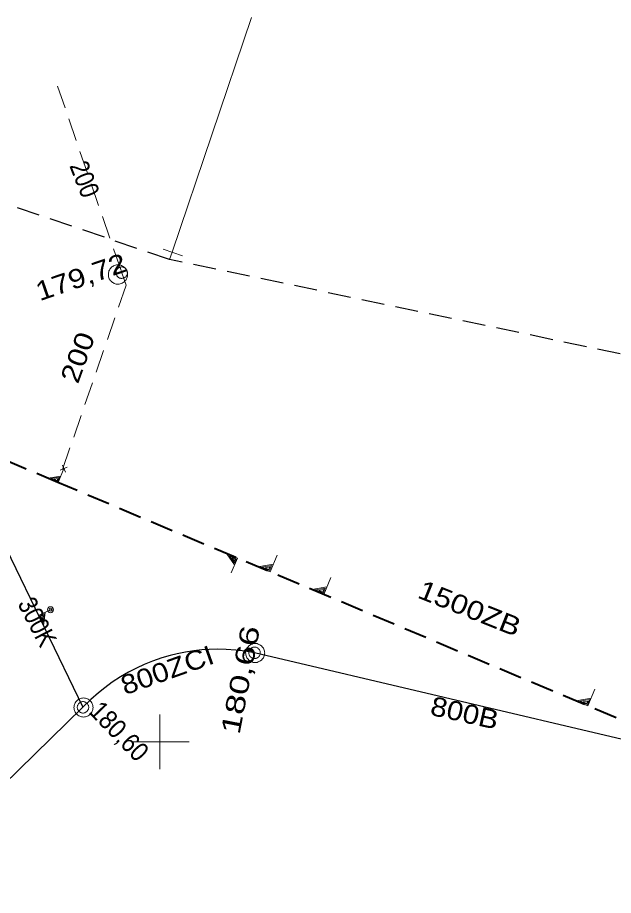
# Model space of a CAD drawing. Extents: x -740851 to -738888, y -1041382 to -1040235.
# Drawn here: x -740357.45 to -740326.27, y -1040408.04 to -1040362.13 of the extents above; entities that cross this region are included whole.
import ezdxf

# ---------------------------------------------------------------- set-up
doc = ezdxf.new("R2010")
doc.units = 0
doc.header["$LTSCALE"] = 0.4
doc.linetypes.add('MEDIUM_DASHED', pattern=[4.5, 3, -1.5])
for name, color, linetype, lineweight in [('1', 7, 'Continuous', 13), ('18', 7, 'Continuous', 13), ('38', 7, 'Continuous', 13), ('48', 7, 'MEDIUM_DASHED', 13), ('8', 7, 'Continuous', 13)]:
    doc.layers.add(name, color=color, linetype=linetype, lineweight=lineweight)

msp = doc.modelspace()

# ---------------------------------------------------------------- linework, layer by layer
at = {"layer": '1'}
for p, q in [((-740350, -1040398.571), (-740350, -1040401.429)), ((-740351.48, -1040400), (-740348.48, -1040400))]:
    msp.add_line(p, q, dxfattribs=at)
at = {"layer": '18'}
for p, q in [((-740355.216, -1040385.791), (-740354.854, -1040385.643)), ((-740355.099, -1040385.533), (-740354.95, -1040385.899))]:
    msp.add_line(p, q, dxfattribs=at)
at = {"layer": '18', "lineweight": 25}
msp.add_line((-740321.54, -1040400.88), (-740345.05, -1040395.35), dxfattribs=at)
at = {"layer": '18'}
for points in [[(-740352.39, -1040376.036), (-740352.339, -1040376.045), (-740352.292, -1040376.064), (-740352.237, -1040376.064), (-740352.182, -1040376.064), (-740352.128, -1040376.065), (-740352.079, -1040376.051), (-740352.029, -1040376.038), (-740351.977, -1040376.016), (-740351.933, -1040375.989), (-740351.89, -1040375.963), (-740351.852, -1040375.923), (-740351.814, -1040375.884), (-740351.777, -1040375.844), (-740351.758, -1040375.797), (-740351.729, -1040375.754), (-740351.72, -1040375.703), (-740351.701, -1040375.655), (-740351.701, -1040375.601), (-740351.701, -1040375.546), (-740351.701, -1040375.491), (-740351.714, -1040375.442), (-740351.727, -1040375.393), (-740351.75, -1040375.34), (-740351.776, -1040375.297), (-740351.802, -1040375.254), (-740351.842, -1040375.216), (-740351.882, -1040375.178), (-740351.921, -1040375.14), (-740351.968, -1040375.121), (-740352.012, -1040375.093), (-740352.063, -1040375.084), (-740352.11, -1040375.065), (-740352.165, -1040375.065), (-740352.219, -1040375.065), (-740352.274, -1040375.065), (-740352.323, -1040375.078), (-740352.372, -1040375.091), (-740352.425, -1040375.113), (-740352.468, -1040375.14), (-740352.512, -1040375.166), (-740352.55, -1040375.206), (-740352.587, -1040375.245), (-740352.625, -1040375.285), (-740352.644, -1040375.332), (-740352.672, -1040375.375), (-740352.682, -1040375.426), (-740352.701, -1040375.474), (-740352.701, -1040375.528), (-740352.701, -1040375.583), (-740352.701, -1040375.638), (-740352.688, -1040375.687), (-740352.674, -1040375.736), (-740352.652, -1040375.789), (-740352.625, -1040375.832), (-740352.599, -1040375.875), (-740352.559, -1040375.913), (-740352.52, -1040375.951), (-740352.48, -1040375.989), (-740352.433, -1040376.008)], [(-740352.111, -1040375.748), (-740352.084, -1040375.759), (-740352.054, -1040375.764), (-740352.024, -1040375.77), (-740351.991, -1040375.77), (-740351.957, -1040375.764), (-740351.928, -1040375.757), (-740351.899, -1040375.749), (-740351.868, -1040375.736), (-740351.842, -1040375.72), (-740351.817, -1040375.705), (-740351.789, -1040375.683), (-740351.767, -1040375.66), (-740351.75, -1040375.635), (-740351.733, -1040375.609), (-740351.722, -1040375.581), (-740351.711, -1040375.554), (-740351.706, -1040375.524), (-740351.7, -1040375.494), (-740351.7, -1040375.461), (-740351.706, -1040375.427), (-740351.713, -1040375.398), (-740351.721, -1040375.369), (-740351.734, -1040375.338), (-740351.75, -1040375.312), (-740351.765, -1040375.287), (-740351.787, -1040375.259), (-740351.81, -1040375.237), (-740351.835, -1040375.22), (-740351.861, -1040375.203), (-740351.889, -1040375.192), (-740351.916, -1040375.181), (-740351.946, -1040375.176), (-740351.976, -1040375.17), (-740352.009, -1040375.17), (-740352.043, -1040375.176), (-740352.072, -1040375.183), (-740352.101, -1040375.191), (-740352.132, -1040375.204), (-740352.158, -1040375.22), (-740352.183, -1040375.235), (-740352.211, -1040375.257), (-740352.233, -1040375.28), (-740352.25, -1040375.305), (-740352.267, -1040375.331), (-740352.278, -1040375.359), (-740352.289, -1040375.386), (-740352.294, -1040375.416), (-740352.3, -1040375.446), (-740352.3, -1040375.479), (-740352.294, -1040375.513), (-740352.287, -1040375.542), (-740352.279, -1040375.571), (-740352.266, -1040375.602), (-740352.25, -1040375.628), (-740352.235, -1040375.653), (-740352.213, -1040375.681), (-740352.19, -1040375.703), (-740352.165, -1040375.72), (-740352.139, -1040375.737)], [(-740344.52, -1040395.36), (-740344.53, -1040395.31), (-740344.53, -1040395.26), (-740344.55, -1040395.21), (-740344.57, -1040395.16), (-740344.59, -1040395.11), (-740344.62, -1040395.07), (-740344.65, -1040395.03), (-740344.69, -1040394.99), (-740344.73, -1040394.96), (-740344.77, -1040394.93), (-740344.82, -1040394.91), (-740344.87, -1040394.89), (-740344.92, -1040394.87), (-740344.97, -1040394.87), (-740345.02, -1040394.86), (-740345.07, -1040394.87), (-740345.12, -1040394.87), (-740345.17, -1040394.89), (-740345.22, -1040394.91), (-740345.27, -1040394.93), (-740345.31, -1040394.96), (-740345.35, -1040394.99), (-740345.39, -1040395.03), (-740345.42, -1040395.07), (-740345.45, -1040395.11), (-740345.47, -1040395.16), (-740345.49, -1040395.21), (-740345.51, -1040395.26), (-740345.51, -1040395.31), (-740345.52, -1040395.36), (-740345.51, -1040395.41), (-740345.51, -1040395.46), (-740345.49, -1040395.51), (-740345.47, -1040395.56), (-740345.45, -1040395.61), (-740345.42, -1040395.65), (-740345.39, -1040395.69), (-740345.35, -1040395.73), (-740345.31, -1040395.76), (-740345.27, -1040395.79), (-740345.22, -1040395.81), (-740345.17, -1040395.83), (-740345.12, -1040395.85), (-740345.07, -1040395.85), (-740345.02, -1040395.86), (-740344.97, -1040395.85), (-740344.92, -1040395.85), (-740344.87, -1040395.83), (-740344.82, -1040395.81), (-740344.77, -1040395.79), (-740344.73, -1040395.76), (-740344.69, -1040395.73), (-740344.65, -1040395.69), (-740344.62, -1040395.65), (-740344.59, -1040395.61), (-740344.57, -1040395.56), (-740344.55, -1040395.51), (-740344.53, -1040395.46), (-740344.53, -1040395.41)], [(-740344.75, -1040395.35), (-740344.75, -1040395.32), (-740344.756, -1040395.29), (-740344.762, -1040395.26), (-740344.774, -1040395.23), (-740344.792, -1040395.2), (-740344.81, -1040395.176), (-740344.828, -1040395.152), (-740344.852, -1040395.128), (-740344.876, -1040395.11), (-740344.9, -1040395.092), (-740344.93, -1040395.074), (-740344.96, -1040395.062), (-740344.99, -1040395.056), (-740345.02, -1040395.05), (-740345.05, -1040395.05), (-740345.08, -1040395.05), (-740345.11, -1040395.056), (-740345.14, -1040395.062), (-740345.17, -1040395.074), (-740345.2, -1040395.092), (-740345.224, -1040395.11), (-740345.248, -1040395.128), (-740345.272, -1040395.152), (-740345.29, -1040395.176), (-740345.308, -1040395.2), (-740345.326, -1040395.23), (-740345.338, -1040395.26), (-740345.344, -1040395.29), (-740345.35, -1040395.32), (-740345.35, -1040395.35), (-740345.35, -1040395.38), (-740345.344, -1040395.41), (-740345.338, -1040395.44), (-740345.326, -1040395.47), (-740345.308, -1040395.5), (-740345.29, -1040395.524), (-740345.272, -1040395.548), (-740345.248, -1040395.572), (-740345.224, -1040395.59), (-740345.2, -1040395.608), (-740345.17, -1040395.626), (-740345.14, -1040395.638), (-740345.11, -1040395.644), (-740345.08, -1040395.65), (-740345.05, -1040395.65), (-740345.02, -1040395.65), (-740344.99, -1040395.644), (-740344.96, -1040395.638), (-740344.93, -1040395.626), (-740344.9, -1040395.608), (-740344.876, -1040395.59), (-740344.852, -1040395.572), (-740344.828, -1040395.548), (-740344.81, -1040395.524), (-740344.792, -1040395.5), (-740344.774, -1040395.47), (-740344.762, -1040395.44), (-740344.756, -1040395.41), (-740344.75, -1040395.38)], [(-740353.5, -1040398.21), (-740353.51, -1040398.16), (-740353.51, -1040398.11), (-740353.53, -1040398.06), (-740353.55, -1040398.01), (-740353.57, -1040397.96), (-740353.6, -1040397.92), (-740353.63, -1040397.88), (-740353.67, -1040397.84), (-740353.71, -1040397.81), (-740353.75, -1040397.78), (-740353.8, -1040397.76), (-740353.85, -1040397.74), (-740353.9, -1040397.72), (-740353.95, -1040397.72), (-740354, -1040397.71), (-740354.05, -1040397.72), (-740354.1, -1040397.72), (-740354.15, -1040397.74), (-740354.2, -1040397.76), (-740354.25, -1040397.78), (-740354.29, -1040397.81), (-740354.33, -1040397.84), (-740354.37, -1040397.88), (-740354.4, -1040397.92), (-740354.43, -1040397.96), (-740354.45, -1040398.01), (-740354.47, -1040398.06), (-740354.49, -1040398.11), (-740354.49, -1040398.16), (-740354.5, -1040398.21), (-740354.49, -1040398.26), (-740354.49, -1040398.31), (-740354.47, -1040398.36), (-740354.45, -1040398.41), (-740354.43, -1040398.46), (-740354.4, -1040398.5), (-740354.37, -1040398.54), (-740354.33, -1040398.58), (-740354.29, -1040398.61), (-740354.25, -1040398.64), (-740354.2, -1040398.66), (-740354.15, -1040398.68), (-740354.1, -1040398.7), (-740354.05, -1040398.7), (-740354, -1040398.71), (-740353.95, -1040398.7), (-740353.9, -1040398.7), (-740353.85, -1040398.68), (-740353.8, -1040398.66), (-740353.75, -1040398.64), (-740353.71, -1040398.61), (-740353.67, -1040398.58), (-740353.63, -1040398.54), (-740353.6, -1040398.5), (-740353.57, -1040398.46), (-740353.55, -1040398.41), (-740353.53, -1040398.36), (-740353.51, -1040398.31), (-740353.51, -1040398.26)], [(-740353.73, -1040398.2), (-740353.73, -1040398.17), (-740353.736, -1040398.14), (-740353.742, -1040398.11), (-740353.754, -1040398.08), (-740353.772, -1040398.05), (-740353.79, -1040398.026), (-740353.808, -1040398.002), (-740353.832, -1040397.978), (-740353.856, -1040397.96), (-740353.88, -1040397.942), (-740353.91, -1040397.924), (-740353.94, -1040397.912), (-740353.97, -1040397.906), (-740354, -1040397.9), (-740354.03, -1040397.9), (-740354.06, -1040397.9), (-740354.09, -1040397.906), (-740354.12, -1040397.912), (-740354.15, -1040397.924), (-740354.18, -1040397.942), (-740354.204, -1040397.96), (-740354.228, -1040397.978), (-740354.252, -1040398.002), (-740354.27, -1040398.026), (-740354.288, -1040398.05), (-740354.306, -1040398.08), (-740354.318, -1040398.11), (-740354.324, -1040398.14), (-740354.33, -1040398.17), (-740354.33, -1040398.2), (-740354.33, -1040398.23), (-740354.324, -1040398.26), (-740354.318, -1040398.29), (-740354.306, -1040398.32), (-740354.288, -1040398.35), (-740354.27, -1040398.374), (-740354.252, -1040398.398), (-740354.228, -1040398.422), (-740354.204, -1040398.44), (-740354.18, -1040398.458), (-740354.15, -1040398.476), (-740354.12, -1040398.488), (-740354.09, -1040398.494), (-740354.06, -1040398.5), (-740354.03, -1040398.5), (-740354, -1040398.5), (-740353.97, -1040398.494), (-740353.94, -1040398.488), (-740353.91, -1040398.476), (-740353.88, -1040398.458), (-740353.856, -1040398.44), (-740353.832, -1040398.422), (-740353.808, -1040398.398), (-740353.79, -1040398.374), (-740353.772, -1040398.35), (-740353.754, -1040398.32), (-740353.742, -1040398.29), (-740353.736, -1040398.26), (-740353.73, -1040398.23)]]:
    msp.add_lwpolyline(points, close=True, dxfattribs=at)
at = {"layer": '18', "linetype": 'MEDIUM_DASHED', "lineweight": 40}
msp.add_lwpolyline([(-740306.23, -1040407.14), (-740355.337, -1040386.443), (-740362.58, -1040383.39)], dxfattribs=at)
at = {"layer": '18'}
for points in [[(-740355.027, -1040385.713), (-740355.335, -1040386.442), (-740355.854, -1040386.223), (-740355.196, -1040386.113)], [(-740355.265, -1040386.17), (-740355.354, -1040386.382), (-740355.687, -1040386.242), (-740355.262, -1040386.171)], [(-740355.336, -1040386.23), (-740355.38, -1040386.336), (-740355.551, -1040386.265), (-740355.332, -1040386.232)], [(-740346.271, -1040391.169), (-740345.947, -1040390.4), (-740346.495, -1040390.169), (-740346.093, -1040390.747)], [(-740346.101, -1040390.653), (-740346.006, -1040390.429), (-740346.357, -1040390.282), (-740346.097, -1040390.655)], [(-740346.107, -1040390.555), (-740346.06, -1040390.443), (-740346.24, -1040390.368), (-740346.104, -1040390.557)], [(-740343.872, -1040390.235), (-740344.243, -1040391.116), (-740344.872, -1040390.851), (-740344.076, -1040390.719)], [(-740344.159, -1040390.787), (-740344.267, -1040391.044), (-740344.669, -1040390.875), (-740344.155, -1040390.789)], [(-740344.244, -1040390.86), (-740344.299, -1040390.989), (-740344.505, -1040390.902), (-740344.24, -1040390.862)], [(-740341.061, -1040391.42), (-740341.433, -1040392.301), (-740342.061, -1040392.036), (-740341.265, -1040391.903)], [(-740341.349, -1040391.972), (-740341.457, -1040392.228), (-740341.858, -1040392.059), (-740341.344, -1040391.974)], [(-740341.434, -1040392.045), (-740341.488, -1040392.173), (-740341.694, -1040392.086), (-740341.43, -1040392.047)], [(-740355.59, -1040393.03), (-740356.35, -1040393.398), (-740356.088, -1040393.94), (-740356.007, -1040393.232)], [(-740356.064, -1040393.309), (-740356.286, -1040393.416), (-740356.118, -1040393.762), (-740356.066, -1040393.305)], [(-740356.125, -1040393.387), (-740356.235, -1040393.441), (-740356.149, -1040393.619), (-740356.126, -1040393.384)], [(-740327.239, -1040397.245), (-740327.61, -1040398.126), (-740328.239, -1040397.861), (-740327.443, -1040397.729)], [(-740327.526, -1040397.798), (-740327.634, -1040398.054), (-740328.036, -1040397.885), (-740327.522, -1040397.8)], [(-740327.611, -1040397.871), (-740327.665, -1040397.999), (-740327.871, -1040397.912), (-740327.607, -1040397.873)]]:
    msp.add_lwpolyline(points, dxfattribs=at)
at = {"layer": '18', "lineweight": 25}
for points in [[(-740358.04, -1040389.9), (-740354.03, -1040398.2), (-740364.11, -1040408.04)], [(-740345.05, -1040395.35), (-740345.542, -1040395.266), (-740346.028, -1040395.208), (-740346.536, -1040395.173), (-740346.991, -1040395.165), (-740347.419, -1040395.176), (-740347.803, -1040395.202), (-740348.223, -1040395.248), (-740348.659, -1040395.316), (-740349.097, -1040395.404), (-740349.466, -1040395.494), (-740349.899, -1040395.621), (-740350.387, -1040395.79), (-740350.822, -1040395.965), (-740351.227, -1040396.151), (-740351.648, -1040396.369), (-740352.061, -1040396.608), (-740352.496, -1040396.891), (-740352.887, -1040397.175), (-740353.215, -1040397.437), (-740353.614, -1040397.789), (-740354.03, -1040398.2)]]:
    msp.add_lwpolyline(points, dxfattribs=at)
at = {"layer": '18'}
for centre, radius in [((-740355.728, -1040393.097), 0.159), ((-740355.726, -1040393.097), 0.0786)]:
    msp.add_circle(centre, radius, dxfattribs=at)
at = {"layer": '38'}
for p, q in [((-740349.37, -1040374.4), (-740345.218, -1040362.126)), ((-740349.498, -1040374.778), (-740349.37, -1040374.4))]:
    msp.add_line(p, q, dxfattribs=at)
at = {"layer": '48'}
msp.add_line((-740355.36, -1040365.72), (-740352, -1040375.47), dxfattribs=at)
msp.add_lwpolyline([(-740352, -1040375.47), (-740351.77, -1040376.13), (-740355.337, -1040386.443)], dxfattribs=at)
at = {"layer": '8'}
msp.add_line((-740348.83, -1040374.583), (-740349.83, -1040374.244), dxfattribs=at)
at = {"layer": '8', "linetype": 'MEDIUM_DASHED', "lineweight": 25}
msp.add_lwpolyline([(-740297.337, -1040386.803), (-740297.74, -1040385.61), (-740349.498, -1040374.778), (-740359.17, -1040371.49)], dxfattribs=at)

# ---------------------------------------------------------------- texts
at = {"layer": '18'}
for s, rotation, width, p in [('200', 291.505, 0.85, (-740354.752, -1040369.876)), ('179,72', 19.016, 1.2, (-740356.293, -1040376.965)), ('200', 69.909, 1.2, (-740354.296, -1040381.329)), ('1500ZB', 338.306, 1.2, (-740336.589, -1040392.445)), ('300K', 297.421, 0.85, (-740357.473, -1040392.784)), ('180,66', 79.066, 1.4, (-740345.843, -1040399.669)), ('800ZCI', 19.617, 1.15, (-740351.828, -1040397.571)), ('800B', 347.399, 1.15, (-740335.916, -1040398.587)), ('180,60', 313.918, 0.9, (-740353.764, -1040398.469))]:
    msp.add_text(s, height=1, rotation=rotation, dxfattribs=dict(at, width=width)).set_placement(p)

doc.saveas('drawing.dxf')
